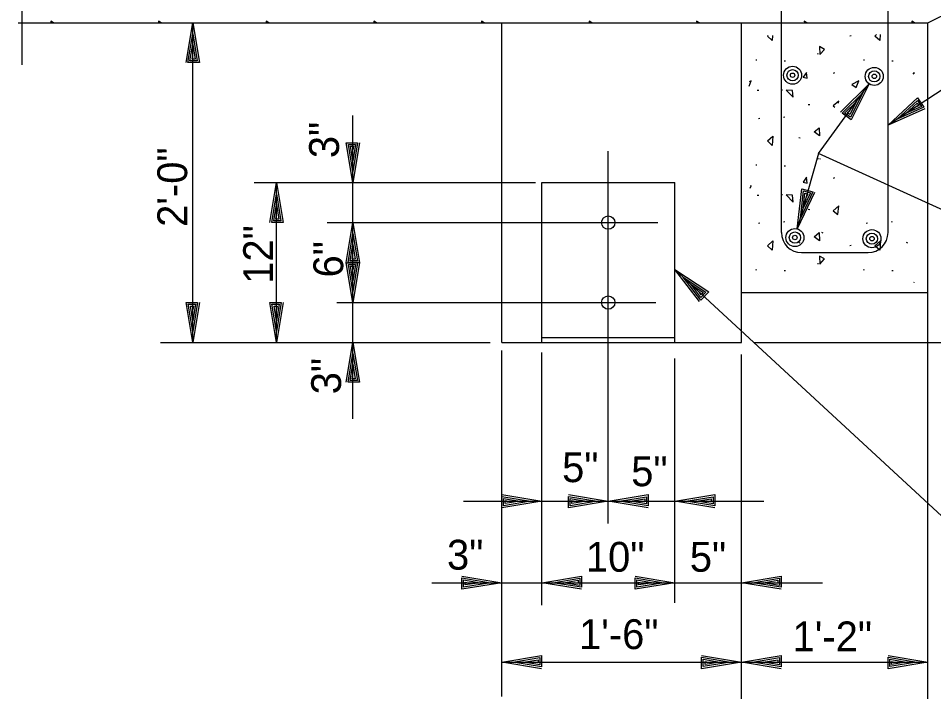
# Model space of a CAD drawing. Extents: x -48 to 108, y -5 to 100.
# Drawn here: x 57.71 to 69.16, y 16.66 to 25.17 of the extents above; entities that cross this region are included whole.
import ezdxf

# ---------------------------------------------------------------- set-up
doc = ezdxf.new("R2010")
doc.units = 0
for name, color, linetype in [('Level 2', 7, 'Continuous'), ('Level 25', 7, 'Continuous'), ('Level 44', 7, 'Continuous'), ('Level 50', 7, 'Continuous')]:
    doc.layers.add(name, color=color, linetype=linetype)

msp = doc.modelspace()

# ---------------------------------------------------------------- linework, layer by layer
at = {"layer": 'Level 2'}
for p, q in [((68.592, 22.492), (68.592, 28.251)), ((67.259, 22.492), (67.259, 28.047)), ((57.759, 24.593), (57.759, 25.574)), ((57.71, 25.117), (69.092, 25.117)), ((59.892, 21.117), (59.892, 25.117)), ((63.759, 21.117), (63.759, 25.117)), ((66.759, 21.117), (66.759, 25.117)), ((69.092, 21.742), (69.092, 25.117)), ((69.521, 24.446), (68.592, 23.835)), ((67.724, 23.48), (68.357, 24.354)), ((61.896, 23.117), (61.896, 23.956)), ((65.092, 20.94), (65.092, 23.513)), ((67.724, 23.48), (67.457, 22.539)), ((69.534, 22.659), (67.724, 23.48)), ((60.659, 23.117), (64.182, 23.117)), ((60.94, 21.117), (60.94, 23.117)), ((61.896, 22.617), (61.896, 23.117)), ((64.259, 23.117), (65.925, 23.117)), ((64.259, 21.117), (64.259, 23.117)), ((65.925, 21.117), (65.925, 23.117)), ((61.576, 22.617), (64.464, 22.617)), ((61.896, 21.617), (61.896, 22.617)), ((64.464, 22.617), (65.711, 22.617)), ((67.509, 22.242), (68.342, 22.242)), ((69.718, 18.523), (65.925, 22.029)), ((66.759, 21.742), (69.092, 21.742)), ((69.092, 16.66), (69.092, 21.742)), ((61.694, 21.617), (64.444, 21.617)), ((61.896, 21.117), (61.896, 21.617)), ((64.444, 21.617), (65.685, 21.617)), ((59.488, 21.117), (63.616, 21.117)), ((61.896, 20.16), (61.896, 21.117)), ((63.759, 21.117), (66.759, 21.117)), ((64.259, 21.18), (65.925, 21.18)), ((66.916, 21.117), (73.094, 21.117)), ((63.759, 16.686), (63.759, 21.016)), ((64.259, 17.832), (64.259, 20.991)), ((66.759, 16.66), (66.759, 20.966)), ((65.092, 18.851), (65.092, 20.94)), ((65.925, 17.858), (65.925, 20.915)), ((63.279, 19.131), (64.259, 19.131)), ((64.259, 19.131), (65.092, 19.131)), ((65.092, 19.131), (65.925, 19.131)), ((65.925, 19.131), (67.037, 19.131)), ((62.886, 18.112), (63.759, 18.112)), ((63.759, 18.112), (64.259, 18.112)), ((64.259, 18.112), (65.925, 18.112)), ((65.925, 18.112), (66.759, 18.112)), ((66.759, 18.112), (67.771, 18.112)), ((63.759, 17.119), (66.759, 17.119)), ((66.759, 17.119), (69.092, 17.119))]:
    msp.add_line(p, q, dxfattribs=at)
for centre in [(65.092, 22.617), (65.092, 21.617)]:
    msp.add_circle(centre, 0.0833, dxfattribs=at)
for centre, start, end in [((67.509, 22.492), 180, 270), ((68.342, 22.492), 270, 0)]:
    msp.add_arc(centre, 0.25, start, end, dxfattribs=at)
at = {"layer": 'Level 25'}
msp.add_line((69.092, 25.117), (73.673, 27.408), dxfattribs=at)
at = {"layer": 'Level 44'}
for p, q in [((68.131, 24.953), (68.116, 24.951)), ((66.952, 24.648), (66.939, 24.65)), ((67.311, 24.636), (67.293, 24.636)), ((67.721, 24.726), (67.708, 24.727)), ((68.299, 24.648), (68.286, 24.65)), ((68.658, 24.636), (68.64, 24.636)), ((67.922, 24.491), (67.906, 24.483)), ((66.974, 24.269), (66.956, 24.269)), ((67.272, 24.276), (67.255, 24.276)), ((67.612, 24.089), (67.594, 24.092)), ((66.988, 23.92), (66.97, 23.915)), ((67.299, 23.938), (67.286, 23.933)), ((67.491, 23.673), (67.477, 23.68)), ((67.721, 23.414), (67.708, 23.415)), ((66.952, 23.336), (66.939, 23.338)), ((67.311, 23.325), (67.293, 23.325)), ((67.922, 23.179), (67.906, 23.171)), ((66.974, 22.958), (66.956, 22.958)), ((67.272, 22.964), (67.255, 22.964)), ((67.612, 22.778), (67.594, 22.781)), ((66.988, 22.609), (66.97, 22.604)), ((67.299, 22.627), (67.286, 22.622)), ((68.335, 22.609), (68.317, 22.604)), ((68.645, 22.627), (68.632, 22.622)), ((67.781, 22.485), (67.766, 22.494)), ((67.491, 22.361), (67.477, 22.368)), ((68.838, 22.361), (68.823, 22.368)), ((68.131, 22.329), (68.116, 22.328)), ((66.952, 22.024), (66.939, 22.027)), ((67.311, 22.013), (67.293, 22.013)), ((67.721, 22.102), (67.708, 22.103)), ((68.299, 22.024), (68.286, 22.027)), ((68.658, 22.013), (68.64, 22.013))]:
    msp.add_line(p, q, dxfattribs=at)
for points in [[(58.152, 25.117), (58.117, 25.136), (58.118, 25.117)], [(59.499, 25.117), (59.464, 25.136), (59.465, 25.117)], [(60.845, 25.117), (60.811, 25.136), (60.812, 25.117)], [(62.192, 25.117), (62.157, 25.136), (62.158, 25.117)], [(63.539, 25.117), (63.504, 25.136), (63.505, 25.117)], [(64.885, 25.117), (64.851, 25.136), (64.852, 25.117)], [(66.232, 25.117), (66.197, 25.136), (66.198, 25.117)], [(67.579, 25.117), (67.544, 25.136), (67.545, 25.117)], [(68.925, 25.117), (68.891, 25.136), (68.892, 25.117)], [(68.491, 24.894), (68.429, 24.951), (68.45, 24.969)], [(68.495, 24.97), (68.491, 24.894)], [(67.144, 24.894), (67.083, 24.951), (67.091, 24.959)], [(67.148, 24.959), (67.144, 24.894)], [(68.92, 24.478), (68.918, 24.496), (68.902, 24.473)], [(66.854, 24.325), (66.879, 24.39), (66.853, 24.377)], [(67.976, 24.137), (67.907, 24.078), (67.925, 24.063)], [(67.973, 24.113), (67.976, 24.137)], [(67.74, 23.42), (67.741, 23.409)], [(67.741, 23.409), (67.745, 23.414)], [(66.867, 23.048), (66.879, 23.078), (66.867, 23.072)], [(68.918, 21.869), (68.918, 21.873), (68.915, 21.869)]]:
    msp.add_lwpolyline(points, dxfattribs=at)
for points in [[(67.741, 24.721), (67.798, 24.785), (67.734, 24.819)], [(67.58, 24.423), (67.571, 24.496), (67.53, 24.435)], [(68.194, 24.308), (68.226, 24.39), (68.138, 24.347)], [(67.397, 24.271), (67.317, 24.276), (67.404, 24.187)], [(67.734, 23.703), (67.67, 23.751), (67.731, 23.805)], [(67.144, 23.582), (67.083, 23.639), (67.151, 23.7)], [(67.58, 23.111), (67.571, 23.184), (67.53, 23.123)], [(67.397, 22.96), (67.317, 22.964), (67.404, 22.875)], [(67.976, 22.826), (67.907, 22.766), (67.964, 22.718)], [(67.734, 22.391), (67.67, 22.439), (67.731, 22.494)], [(67.144, 22.271), (67.083, 22.328), (67.151, 22.389)], [(68.491, 22.271), (68.429, 22.328), (68.498, 22.389)], [(67.741, 22.098), (67.798, 22.162), (67.734, 22.196)]]:
    msp.add_lwpolyline(points, close=True, dxfattribs=at)
at = {"layer": 'Level 50'}
for p, q in [((59.892, 25.117), (59.892, 25.117)), ((59.892, 24.979), (59.892, 24.979)), ((68.357, 24.354), (68.357, 24.354)), ((68.276, 24.242), (68.276, 24.242)), ((68.592, 23.835), (68.592, 23.835)), ((68.708, 23.912), (68.708, 23.912)), ((61.896, 23.256), (61.896, 23.256)), ((61.896, 23.256), (61.896, 23.256)), ((60.94, 23.117), (60.94, 23.117)), ((61.896, 23.117), (61.896, 23.117)), ((61.896, 23.117), (61.896, 23.117)), ((60.94, 22.979), (60.94, 22.979)), ((61.896, 22.617), (61.896, 22.617)), ((61.896, 22.617), (61.896, 22.617)), ((67.495, 22.672), (67.495, 22.672)), ((61.896, 22.479), (61.896, 22.479)), ((61.896, 22.479), (61.896, 22.479)), ((67.457, 22.539), (67.457, 22.539)), ((65.925, 22.029), (65.925, 22.029)), ((66.027, 21.935), (66.027, 21.935)), ((61.896, 21.756), (61.896, 21.756)), ((61.896, 21.617), (61.896, 21.617)), ((59.892, 21.256), (59.892, 21.256)), ((60.94, 21.256), (60.94, 21.256)), ((59.892, 21.117), (59.892, 21.117)), ((60.94, 21.117), (60.94, 21.117)), ((61.896, 21.117), (61.896, 21.117)), ((61.896, 20.979), (61.896, 20.979)), ((64.12, 19.131), (64.12, 19.131)), ((64.259, 19.131), (64.259, 19.131)), ((64.953, 19.131), (64.953, 19.131)), ((65.092, 19.131), (65.092, 19.131)), ((65.092, 19.131), (65.092, 19.131)), ((65.231, 19.131), (65.231, 19.131)), ((65.925, 19.131), (65.925, 19.131)), ((66.064, 19.131), (66.064, 19.131)), ((63.62, 18.112), (63.62, 18.112)), ((63.759, 18.112), (63.759, 18.112)), ((64.259, 18.112), (64.259, 18.112)), ((64.397, 18.112), (64.397, 18.112)), ((65.787, 18.112), (65.787, 18.112)), ((65.925, 18.112), (65.925, 18.112)), ((66.759, 18.112), (66.759, 18.112)), ((66.897, 18.112), (66.897, 18.112)), ((63.759, 17.119), (63.759, 17.119)), ((63.897, 17.119), (63.897, 17.119)), ((66.62, 17.119), (66.62, 17.119)), ((66.759, 17.119), (66.759, 17.119)), ((66.759, 17.119), (66.759, 17.119)), ((66.897, 17.119), (66.897, 17.119)), ((68.953, 17.119), (68.953, 17.119)), ((69.092, 17.119), (69.092, 17.119))]:
    msp.add_line(p, q, dxfattribs=at)
for points in [[(59.809, 24.619), (59.892, 25.117), (59.975, 24.619), (59.833, 24.619), (59.892, 24.979), (59.948, 24.64), (59.857, 24.64), (59.892, 24.845), (59.921, 24.661), (59.884, 24.661), (59.892, 24.707)], [(67.997, 23.999), (68.357, 24.354), (68.131, 23.902), (68.017, 23.985), (68.276, 24.242), (68.122, 23.935), (68.049, 23.988), (68.197, 24.134), (68.113, 23.968), (68.083, 23.989), (68.116, 24.021)], [(69.054, 24.041), (68.592, 23.835), (68.963, 24.179), (69.041, 24.061), (68.708, 23.912), (68.96, 24.145), (69.01, 24.069), (68.819, 23.985), (68.957, 24.111), (68.977, 24.079), (68.935, 24.061)], [(61.978, 23.616), (61.896, 23.117), (61.813, 23.616), (61.954, 23.616), (61.896, 23.256), (61.84, 23.595), (61.93, 23.595), (61.896, 23.389), (61.866, 23.573), (61.904, 23.573), (61.896, 23.528)], [(61.978, 23.616), (61.896, 23.117), (61.813, 23.616), (61.954, 23.616), (61.896, 23.256), (61.84, 23.595), (61.93, 23.595), (61.896, 23.389), (61.866, 23.573), (61.904, 23.573), (61.896, 23.528)], [(60.857, 22.619), (60.94, 23.117), (61.022, 22.619), (60.881, 22.619), (60.94, 22.979), (60.996, 22.64), (60.905, 22.64), (60.94, 22.845), (60.969, 22.661), (60.932, 22.661), (60.94, 22.707)], [(67.673, 22.996), (67.457, 22.539), (67.514, 23.041), (67.65, 23.002), (67.495, 22.672), (67.534, 23.013), (67.621, 22.988), (67.531, 22.8), (67.553, 22.985), (67.589, 22.975), (67.569, 22.934)], [(61.813, 22.119), (61.896, 22.617), (61.978, 22.119), (61.837, 22.119), (61.896, 22.479), (61.952, 22.14), (61.861, 22.14), (61.896, 22.345), (61.925, 22.161), (61.888, 22.161), (61.896, 22.207)], [(61.813, 22.119), (61.896, 22.617), (61.978, 22.119), (61.837, 22.119), (61.896, 22.479), (61.952, 22.14), (61.861, 22.14), (61.896, 22.345), (61.925, 22.161), (61.888, 22.161), (61.896, 22.207)], [(61.978, 22.116), (61.896, 21.617), (61.813, 22.116), (61.954, 22.116), (61.896, 21.756), (61.84, 22.095), (61.93, 22.095), (61.896, 21.889), (61.866, 22.073), (61.904, 22.073), (61.896, 22.028)], [(66.235, 21.63), (65.925, 22.029), (66.348, 21.751), (66.252, 21.648), (66.027, 21.935), (66.314, 21.746), (66.252, 21.68), (66.125, 21.845), (66.28, 21.741), (66.255, 21.714), (66.227, 21.75)], [(59.975, 21.616), (59.892, 21.117), (59.809, 21.616), (59.951, 21.616), (59.892, 21.256), (59.836, 21.595), (59.927, 21.595), (59.892, 21.389), (59.863, 21.573), (59.9, 21.573), (59.892, 21.528)], [(61.022, 21.616), (60.94, 21.117), (60.857, 21.616), (60.998, 21.616), (60.94, 21.256), (60.884, 21.595), (60.974, 21.595), (60.94, 21.389), (60.91, 21.573), (60.948, 21.573), (60.94, 21.528)], [(61.813, 20.619), (61.896, 21.117), (61.978, 20.619), (61.837, 20.619), (61.896, 20.979), (61.952, 20.64), (61.861, 20.64), (61.896, 20.845), (61.925, 20.661), (61.888, 20.661), (61.896, 20.707)], [(63.76, 19.214), (64.259, 19.131), (63.76, 19.049), (63.76, 19.19), (64.12, 19.131), (63.781, 19.075), (63.781, 19.166), (63.987, 19.131), (63.803, 19.102), (63.803, 19.139), (63.848, 19.131)], [(64.593, 19.214), (65.092, 19.131), (64.593, 19.049), (64.593, 19.19), (64.953, 19.131), (64.615, 19.075), (64.615, 19.166), (64.82, 19.131), (64.636, 19.102), (64.636, 19.139), (64.681, 19.131)], [(65.591, 19.049), (65.092, 19.131), (65.591, 19.214), (65.591, 19.073), (65.231, 19.131), (65.569, 19.187), (65.569, 19.097), (65.364, 19.131), (65.548, 19.161), (65.548, 19.123), (65.503, 19.131)], [(66.424, 19.049), (65.925, 19.131), (66.424, 19.214), (66.424, 19.073), (66.064, 19.131), (66.403, 19.187), (66.403, 19.097), (66.197, 19.131), (66.381, 19.161), (66.381, 19.123), (66.336, 19.131)], [(63.26, 18.195), (63.759, 18.112), (63.26, 18.03), (63.26, 18.171), (63.62, 18.112), (63.281, 18.056), (63.281, 18.147), (63.487, 18.112), (63.303, 18.083), (63.303, 18.12), (63.348, 18.112)], [(64.757, 18.03), (64.259, 18.112), (64.757, 18.195), (64.757, 18.054), (64.397, 18.112), (64.736, 18.168), (64.736, 18.078), (64.531, 18.112), (64.715, 18.142), (64.715, 18.104), (64.669, 18.112)], [(65.427, 18.195), (65.925, 18.112), (65.427, 18.03), (65.427, 18.171), (65.787, 18.112), (65.448, 18.056), (65.448, 18.147), (65.653, 18.112), (65.469, 18.083), (65.469, 18.12), (65.515, 18.112)], [(67.257, 18.03), (66.759, 18.112), (67.257, 18.195), (67.257, 18.054), (66.897, 18.112), (67.236, 18.168), (67.236, 18.078), (67.031, 18.112), (67.215, 18.142), (67.215, 18.104), (67.169, 18.112)], [(64.257, 17.036), (63.759, 17.119), (64.257, 17.202), (64.257, 17.06), (63.897, 17.119), (64.236, 17.175), (64.236, 17.084), (64.031, 17.119), (64.215, 17.148), (64.215, 17.111), (64.169, 17.119)], [(66.26, 17.202), (66.759, 17.119), (66.26, 17.036), (66.26, 17.178), (66.62, 17.119), (66.281, 17.063), (66.281, 17.154), (66.487, 17.119), (66.303, 17.09), (66.303, 17.127), (66.348, 17.119)], [(67.257, 17.036), (66.759, 17.119), (67.257, 17.202), (67.257, 17.06), (66.897, 17.119), (67.236, 17.175), (67.236, 17.084), (67.031, 17.119), (67.215, 17.148), (67.215, 17.111), (67.169, 17.119)], [(68.593, 17.202), (69.092, 17.119), (68.593, 17.036), (68.593, 17.178), (68.953, 17.119), (68.615, 17.063), (68.615, 17.154), (68.82, 17.119), (68.636, 17.09), (68.636, 17.127), (68.681, 17.119)]]:
    msp.add_lwpolyline(points, dxfattribs=at)
for centre, radius in [((67.398, 24.461), 0.113), ((67.398, 24.461), 0.0703), ((68.42, 24.447), 0.113), ((68.42, 24.447), 0.0703), ((67.398, 24.461), 0.0281), ((68.42, 24.447), 0.0281), ((67.427, 22.43), 0.113), ((67.427, 22.43), 0.0703), ((67.427, 22.43), 0.0281), ((68.391, 22.416), 0.113), ((68.391, 22.416), 0.0703), ((68.391, 22.416), 0.0281)]:
    msp.add_circle(centre, radius, dxfattribs=at)

# ---------------------------------------------------------------- texts
at = {"layer": 'Level 25'}
for s, p in [('3"', (61.722, 23.424)), ('2\'-0"', (59.823, 22.564)), ('12"', (60.897, 21.852)), ('6"', (61.775, 21.931)), ('3"', (61.748, 20.469))]:
    msp.add_text(s, height=0.3733, rotation=90, dxfattribs=at).set_placement(p)
for s, p in [('5"', (64.514, 19.37)), ('5"', (65.379, 19.319)), ('3"', (63.074, 18.275)), ('10"', (64.812, 18.249)), ('5"', (66.112, 18.249)), ('1\'-6"', (64.726, 17.281)), ('1\'-2"', (67.398, 17.253))]:
    msp.add_text(s, height=0.3733, dxfattribs=at).set_placement(p)

doc.saveas('drawing.dxf')
